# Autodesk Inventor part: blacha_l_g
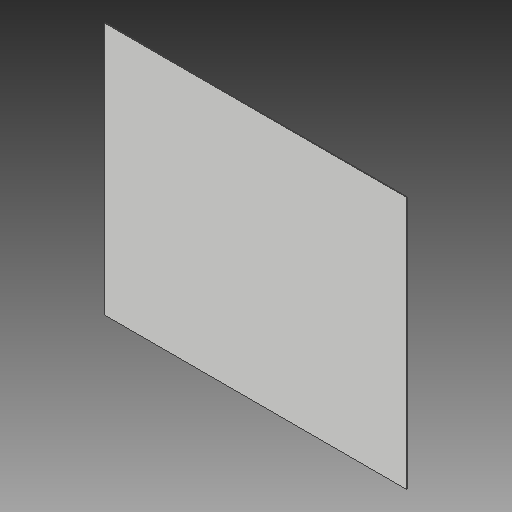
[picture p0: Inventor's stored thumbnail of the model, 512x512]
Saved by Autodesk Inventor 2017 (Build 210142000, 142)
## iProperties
Created: 2020-06
Part Number: blacha_l_g
Material: Generic
Document SubType Name: Modeling
Designer: WindowsX
Density: 1 g/cm^3
Appearance: Default
Mass: 3504.6 g
Surface Area: 23494.2 cm^2
Volume: 3504.6 cm^3
Author: WindowsX
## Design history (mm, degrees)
sketch "Szkic1"
  geometry: L1 (0, 0)-(1180, 0); L2 (1180, 0)-(1180, 990); L3 (1180, 990)-(0, 990); L4 (0, 990)-(0, 0)
  constraints: 8 end point, 2 parallel, 1 horizontal, 1 perpendicular
  dimensions: "d0" = 1180 distance of L2.end L3.end; "d1" = 990 distance of L1.start L3.end
extrude "Wyciągnięcie proste1" new body sketch "Szkic1" distance "d2" = 3; taper "d3" = 0 deg
node "Bryła1"
